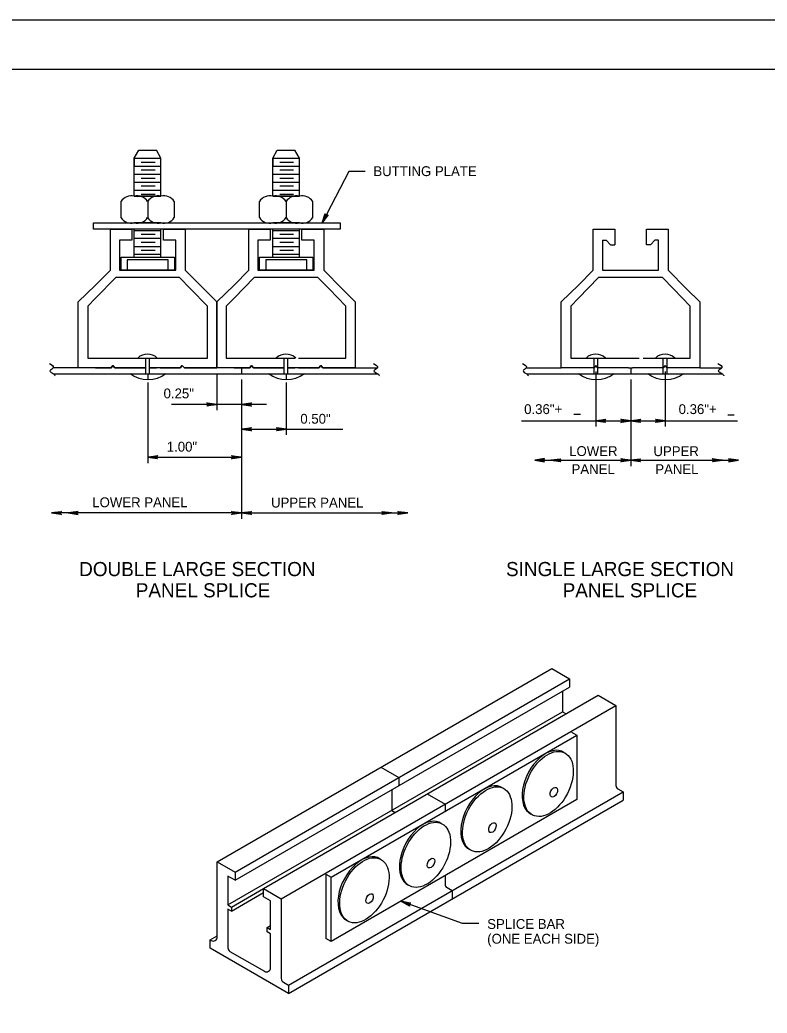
# Model space of a CAD drawing. Extents: x 650495 to 652241, y 298458 to 299646.
# Drawn here: x 651586.1 to 651813.4, y 299343.6 to 299645.6 of the extents above; entities that cross this region are included whole.
import ezdxf

# ---------------------------------------------------------------- set-up
doc = ezdxf.new("R2010")
doc.units = 0
for name, color, linetype in [('1', 7, 'Continuous'), ('2', 7, 'Continuous'), ('3', 7, 'Continuous'), ('PLT-BNDY', 7, 'Continuous')]:
    doc.layers.add(name, color=color, linetype=linetype)

# ---------------------------------------------------------------- blocks, each defined once
blk = doc.blocks.new('RARROW')
at = {"layer": '3'}
blk.add_lwpolyline([(-2.2695, 0.285), (-2.184875, 0.12075), (0, 0), (-2.2695, 0.285), (-2.38575, 0.384625), (0, 0), (-2.183125, -0.108), (-2.262875, -0.2705), (0, 0), (-2.38575, -0.379125), (-2.262875, -0.2705)], dxfattribs=at)

msp = doc.modelspace()

# ---------------------------------------------------------------- linework, layer by layer
at = {"layer": '1'}
msp.add_line((651376.31, 299630.63), (652162.31, 299630.63), dxfattribs=at)
at = {"layer": '2'}
for p, q in [((651620.9, 299603.62), (651622.28, 299606)), ((651622.28, 299606), (651627.65, 299606)), ((651629.03, 299603.62), (651627.65, 299606)), ((651663.03, 299603.62), (651664.4, 299606)), ((651664.4, 299606), (651669.78, 299606)), ((651671.15, 299603.62), (651669.78, 299606)), ((651620.9, 299603.62), (651629.03, 299603.62)), ((651620.9, 299603.62), (651620.9, 299601.12)), ((651620.9, 299592), (651620.9, 299603.62)), ((651629.03, 299592), (651629.03, 299603.62)), ((651663.03, 299603.62), (651671.15, 299603.62)), ((651663.03, 299603.62), (651663.03, 299601.12)), ((651663.03, 299592), (651663.03, 299603.62)), ((651671.15, 299592), (651671.15, 299603.62)), ((651620.9, 299601.12), (651629.03, 299601.12)), ((651623.03, 299602.37), (651627.28, 299602.37)), ((651623.03, 299600), (651627.28, 299600)), ((651663.03, 299601.12), (651671.15, 299601.12)), ((651665.15, 299602.37), (651669.4, 299602.37)), ((651665.15, 299600), (651669.4, 299600)), ((651620.9, 299598.75), (651629.03, 299598.75)), ((651623.03, 299597.5), (651627.28, 299597.5)), ((651663.03, 299598.75), (651671.15, 299598.75)), ((651665.15, 299597.5), (651669.4, 299597.5)), ((651620.9, 299596.25), (651629.03, 299596.25)), ((651620.9, 299593.87), (651629.03, 299593.87)), ((651623.03, 299595.12), (651627.28, 299595.12)), ((651663.03, 299596.25), (651671.15, 299596.25)), ((651663.03, 299593.87), (651671.15, 299593.87)), ((651665.15, 299595.12), (651669.4, 299595.12)), ((651616.9, 299585.5), (651616.9, 299590.37)), ((651620.9, 299592), (651629.03, 299592)), ((651629.03, 299592), (651620.9, 299592)), ((651623.03, 299592.62), (651627.28, 299592.62)), ((651625.03, 299590.37), (651625.03, 299585.5)), ((651633.15, 299585.5), (651633.15, 299590.37)), ((651659.03, 299585.5), (651659.03, 299590.37)), ((651663.03, 299592), (651671.15, 299592)), ((651671.15, 299592), (651663.03, 299592)), ((651665.15, 299592.62), (651669.4, 299592.62)), ((651667.15, 299590.37), (651667.15, 299585.5)), ((651675.28, 299585.5), (651675.28, 299590.37)), ((651629.03, 299583.87), (651620.9, 299583.87)), ((651620.9, 299573.5), (651620.9, 299582)), ((651620.9, 299581.62), (651629.03, 299581.62)), ((651629.03, 299573.5), (651629.03, 299582)), ((651671.15, 299583.87), (651663.03, 299583.87)), ((651663.03, 299573.5), (651663.03, 299582)), ((651663.03, 299581.62), (651671.15, 299581.62)), ((651671.15, 299573.5), (651671.15, 299582)), ((651760.53, 299571.12), (651760.53, 299582)), ((651760.53, 299582), (651767.03, 299582)), ((651767.03, 299582), (651767.03, 299577.25)), ((651776.66, 299577.25), (651776.66, 299582)), ((651776.66, 299582), (651783.28, 299582)), ((651783.28, 299582), (651783.28, 299572.25)), ((651620.9, 299579.25), (651629.03, 299579.25)), ((651623.03, 299580.5), (651627.28, 299580.5)), ((651663.03, 299579.25), (651671.15, 299579.25)), ((651665.15, 299580.5), (651669.4, 299580.5)), ((651763.28, 299578.62), (651764.41, 299578.62)), ((651763.28, 299578.62), (651763.28, 299569.5)), ((651765.78, 299577.25), (651764.41, 299578.62)), ((651777.91, 299577.25), (651779.28, 299578.62)), ((651780.41, 299578.62), (651779.28, 299578.62)), ((651780.41, 299569.5), (651780.41, 299578.62)), ((651620.9, 299576.75), (651629.03, 299576.75)), ((651623.03, 299578), (651627.28, 299578)), ((651623.03, 299575.62), (651627.28, 299575.62)), ((651663.03, 299576.75), (651671.15, 299576.75)), ((651665.15, 299578), (651669.4, 299578)), ((651665.15, 299575.62), (651669.4, 299575.62)), ((651765.78, 299577.25), (651767.03, 299577.25)), ((651777.91, 299577.25), (651776.66, 299577.25)), ((651616.9, 299569.5), (651616.9, 299573.5)), ((651616.9, 299573.5), (651633.15, 299573.5)), ((651620.9, 299574.37), (651629.03, 299574.37)), ((651633.15, 299573.5), (651633.15, 299569.5)), ((651659.03, 299569.5), (651659.03, 299573.5)), ((651659.03, 299573.5), (651675.28, 299573.5)), ((651663.03, 299574.37), (651671.15, 299574.37)), ((651675.28, 299573.5), (651675.28, 299569.5)), ((651633.15, 299569.5), (651616.9, 299569.5)), ((651675.28, 299569.5), (651659.03, 299569.5)), ((651763.28, 299569.5), (651780.41, 299569.5)), ((651624.4, 299538), (651624.4, 299542.75)), ((651625.53, 299538), (651625.53, 299542.75)), ((651666.53, 299538), (651666.53, 299542.75)), ((651667.65, 299538), (651667.65, 299542.75)), ((651760.78, 299538), (651760.78, 299542.75)), ((651761.91, 299538), (651761.91, 299542.75)), ((651781.78, 299538), (651781.78, 299542.75)), ((651783.03, 299538), (651783.03, 299542.75)), ((651603.9, 299539.87), (651596.28, 299539.87)), ((651653.53, 299539.87), (651653.53, 299538)), ((651688.15, 299539.87), (651694.9, 299539.87)), ((651740.16, 299539.87), (651750.78, 299539.87)), ((651771.28, 299539.87), (651772.41, 299539.87)), ((651771.91, 299539.87), (651771.91, 299538)), ((651792.91, 299539.87), (651799.66, 299539.87)), ((651596.28, 299538), (651695.03, 299538)), ((651625.03, 299538), (651625.03, 299536.26)), ((651646.03, 299538.12), (651646.03, 299526.93)), ((651653.53, 299536.25), (651653.53, 299493.86)), ((651666.53, 299538), (651667.65, 299538)), ((651667.15, 299538), (651667.15, 299536.26)), ((651740.28, 299538), (651799.78, 299538)), ((651760.78, 299538), (651761.91, 299538)), ((651761.28, 299538.75), (651761.28, 299521.95)), ((651771.28, 299538), (651772.41, 299538)), ((651771.91, 299536.25), (651771.91, 299509.95)), ((651781.78, 299538), (651783.03, 299538)), ((651782.41, 299538.75), (651782.41, 299521.95)), ((651625.03, 299535.41), (651625.03, 299510.88)), ((651667.15, 299535.36), (651667.15, 299519.41)), ((651646.03, 299528.68), (651632.28, 299528.68)), ((651661.12, 299528.68), (651646.03, 299528.68)), ((651756.6, 299525.58), (651754.6, 299525.58)), ((651803.39, 299525.39), (651801.4, 299525.39)), ((651653.53, 299521.16), (651684.31, 299521.16)), ((651738.72, 299523.7), (651804.39, 299523.7)), ((651782.41, 299523.7), (651782.41, 299523.7)), ((651625.03, 299512.63), (651653.53, 299512.63)), ((651743.17, 299511.7), (651771.91, 299511.7)), ((651771.91, 299511.7), (651803.33, 299511.7)), ((651653.53, 299495.68), (651595.78, 299495.68)), ((651653.53, 299495.68), (651704.13, 299495.68)), ((651646.16, 299389.62), (651747.92, 299448.37)), ((651651.57, 299386.49), (651753.33, 299445.24)), ((651651.57, 299383.99), (651753.33, 299442.74)), ((651660.24, 299381.49), (651761.99, 299440.24)), ((651665.65, 299378.37), (651767.41, 299437.12)), ((651649.41, 299376.49), (651751.17, 299435.24)), ((651753.87, 299429.02), (651755.5, 299428.08)), ((651751.72, 299422.82), (651751.72, 299422.82)), ((651667.81, 299352.12), (651769.57, 299410.87)), ((651733.05, 299412.04), (651733.05, 299412.04)), ((651667.81, 299349.62), (651769.57, 299408.37)), ((651755.5, 299408.52), (651755.5, 299408.52)), ((651741.62, 299404.1), (651741.62, 299404.1)), ((651714.38, 299401.26), (651714.38, 299401.26)), ((651736.82, 299397.74), (651736.82, 299397.74)), ((651722.95, 299393.32), (651722.95, 299393.32)), ((651646.16, 299389.62), (651646.16, 299389.62)), ((651695.7, 299390.48), (651695.7, 299390.48)), ((651679.18, 299385.89), (651679.18, 299366.33)), ((651679.18, 299385.89), (651680.8, 299384.95)), ((651718.15, 299386.96), (651718.15, 299386.96)), ((651704.28, 299382.54), (651704.28, 299382.54)), ((651650.49, 299375.87), (651660.24, 299381.49)), ((651650.49, 299374.62), (651660.24, 299380.24)), ((651699.48, 299376.17), (651699.48, 299376.17)), ((651661.32, 299369.62), (651662.4, 299370.24)), ((651685.6, 299371.76), (651685.6, 299371.76)), ((651644, 299365.87), (651646.16, 299367.12)), ((651680.8, 299365.39), (651679.18, 299366.33)), ((651680.8, 299365.39), (651680.8, 299365.39)), ((651650.03, 299362.38), (651660.53, 299356.33))]:
    msp.add_line(p, q, dxfattribs=at)
for points in [[(651691.15, 299599.5), (651686.15, 299599.5), (651678.09, 299583.87)], [(651613.65, 299571.12), (651613.65, 299582), (651620.15, 299582), (651620.15, 299578.62), (651616.4, 299578.62), (651616.4, 299571.12)], [(651633.53, 299572.25), (651633.53, 299578.62), (651629.78, 299578.62), (651629.78, 299582), (651636.4, 299582), (651636.4, 299572.25)], [(651655.78, 299571.12), (651655.78, 299582), (651662.28, 299582), (651662.28, 299578.62), (651658.53, 299578.62), (651658.53, 299571.12)], [(651675.65, 299572.25), (651675.65, 299578.62), (651671.9, 299578.62), (651671.9, 299582), (651678.53, 299582), (651678.53, 299572.25)], [(651628.78, 299569.5), (651633.53, 299569.5), (651633.53, 299572.25)], [(651636.4, 299572.25), (651636.4, 299569.5), (651642.03, 299563.87)], [(651670.9, 299569.5), (651675.65, 299569.5), (651675.65, 299572.25)], [(651678.53, 299572.25), (651678.53, 299569.5), (651684.15, 299563.87)], [(651783.28, 299572.25), (651783.28, 299569.5), (651788.91, 299563.87)], [(651609.15, 299565), (651613.65, 299569.5), (651613.65, 299571.12)], [(651616.4, 299571.12), (651616.4, 299569.5), (651623.78, 299569.5)], [(651623.78, 299569.5), (651625.03, 299569.5)], [(651625.03, 299569.5), (651628.78, 299569.5)], [(651651.28, 299565), (651655.78, 299569.5), (651655.78, 299571.12)], [(651658.53, 299571.12), (651658.53, 299569.5), (651665.9, 299569.5)], [(651665.9, 299569.5), (651667.15, 299569.5)], [(651667.15, 299569.5), (651670.9, 299569.5)], [(651756.03, 299565), (651760.53, 299569.5), (651760.53, 299571.12)], [(651771.91, 299569.5), (651775.66, 299569.5)], [(651615.28, 299567.25), (651609.15, 299561)], [(651623.78, 299567.25), (651615.28, 299567.25)], [(651625.03, 299567.25), (651623.78, 299567.25)], [(651628.78, 299567.25), (651625.03, 299567.25)], [(651634.65, 299567.25), (651628.78, 299567.25)], [(651638.03, 299563.87), (651634.65, 299567.25)], [(651657.4, 299567.25), (651651.28, 299561)], [(651665.9, 299567.25), (651657.4, 299567.25)], [(651667.15, 299567.25), (651665.9, 299567.25)], [(651670.9, 299567.25), (651667.15, 299567.25)], [(651676.78, 299567.25), (651670.9, 299567.25)], [(651680.15, 299563.87), (651676.78, 299567.25)], [(651762.16, 299567.25), (651756.03, 299561)], [(651770.66, 299567.25), (651762.16, 299567.25)], [(651771.91, 299567.25), (651770.66, 299567.25)], [(651775.66, 299567.25), (651771.91, 299567.25)], [(651781.53, 299567.25), (651775.66, 299567.25)], [(651784.91, 299563.87), (651781.53, 299567.25)], [(651609.15, 299539.87), (651603.9, 299539.87), (651603.9, 299559.87), (651609.15, 299565)], [(651643.15, 299549.62), (651643.15, 299558.62), (651638.03, 299563.87)], [(651642.03, 299563.87), (651646.03, 299559.87), (651646.03, 299549.62)], [(651651.28, 299539.87), (651646.03, 299539.87), (651646.03, 299559.87), (651651.28, 299565)], [(651685.28, 299549.62), (651685.28, 299558.62), (651680.15, 299563.87)], [(651684.15, 299563.87), (651688.15, 299559.87), (651688.15, 299549.62)], [(651756.03, 299539.87), (651750.78, 299539.87), (651750.78, 299559.87), (651756.03, 299565)], [(651790.03, 299549.62), (651790.03, 299558.62), (651784.91, 299563.87)], [(651788.91, 299563.87), (651792.91, 299559.87), (651792.91, 299549.62)], [(651609.15, 299561), (651606.78, 299558.62), (651606.78, 299542.75), (651609.15, 299542.75)], [(651651.28, 299561), (651648.9, 299558.62), (651648.9, 299542.75), (651651.28, 299542.75)], [(651756.03, 299561), (651753.66, 299558.62), (651753.66, 299542.75), (651756.03, 299542.75)], [(651628.78, 299542.75), (651643.15, 299542.75), (651643.15, 299549.62)], [(651646.03, 299549.62), (651646.03, 299539.87), (651636.15, 299539.87), (651635.53, 299540.5), (651634.9, 299539.87), (651628.78, 299539.87)], [(651670.9, 299542.75), (651685.28, 299542.75), (651685.28, 299549.62)], [(651688.15, 299549.62), (651688.15, 299539.87), (651678.28, 299539.87), (651677.65, 299540.5), (651677.03, 299539.87), (651670.9, 299539.87)], [(651775.66, 299542.75), (651790.03, 299542.75), (651790.03, 299549.62)], [(651792.91, 299549.62), (651792.91, 299539.87), (651783.03, 299539.87), (651782.41, 299540.5), (651781.78, 299539.87), (651775.66, 299539.87)], [(651609.15, 299542.75), (651625.03, 299542.75)], [(651625.03, 299542.75), (651627.65, 299542.75)], [(651627.65, 299542.75), (651628.78, 299542.75)], [(651651.28, 299542.75), (651667.15, 299542.75)], [(651667.15, 299542.75), (651669.78, 299542.75)], [(651756.03, 299542.75), (651771.91, 299542.75)], [(651771.91, 299542.75), (651774.53, 299542.75)], [(651609.15, 299539.87), (651603.9, 299539.87)], [(651609.15, 299539.87), (651613.9, 299539.87), (651614.4, 299540.5), (651615.03, 299539.87), (651624.4, 299539.87)], [(651624.4, 299539.87), (651615.03, 299539.87), (651614.4, 299540.5), (651613.9, 299539.87), (651609.15, 299539.87)], [(651625.53, 299539.87), (651627.65, 299539.87)], [(651627.65, 299539.87), (651625.53, 299539.87)], [(651628.78, 299539.87), (651627.65, 299539.87)], [(651628.78, 299539.87), (651627.65, 299539.87)], [(651628.78, 299539.87), (651634.9, 299539.87), (651635.53, 299540.5), (651636.15, 299539.87), (651646.03, 299539.87)], [(651651.28, 299539.87), (651646.03, 299539.87)], [(651651.28, 299539.87), (651656.03, 299539.87), (651656.53, 299540.5), (651657.15, 299539.87), (651666.53, 299539.87)], [(651666.53, 299539.87), (651657.15, 299539.87), (651656.53, 299540.5), (651656.03, 299539.87), (651651.28, 299539.87)], [(651667.65, 299539.87), (651669.78, 299539.87)], [(651667.65, 299539.87), (651669.78, 299539.87)], [(651669.78, 299539.87), (651667.65, 299539.87)], [(651670.9, 299539.87), (651669.78, 299539.87)], [(651670.9, 299539.87), (651669.78, 299539.87)], [(651670.9, 299539.87), (651669.78, 299539.87)], [(651670.9, 299539.87), (651677.03, 299539.87), (651677.65, 299540.5), (651678.28, 299539.87), (651688.15, 299539.87)], [(651756.03, 299539.87), (651750.78, 299539.87)], [(651771.28, 299539.87), (651761.91, 299539.87), (651761.28, 299540.5), (651760.78, 299539.87), (651756.03, 299539.87)], [(651774.53, 299539.87), (651772.41, 299539.87)], [(651775.66, 299539.87), (651774.53, 299539.87)], [(651747.92, 299448.37), (651753.33, 299445.24), (651753.33, 299442.74)], [(651751.17, 299441.49), (651751.17, 299435.24), (651752.25, 299434.62)], [(651761.99, 299440.24), (651767.41, 299437.12), (651767.41, 299412.84)], [(651680.8, 299384.95), (651755.5, 299428.08), (651755.5, 299408.52), (651680.8, 299365.39), (651680.8, 299384.95)], [(651695.96, 299418.37), (651701.37, 299415.24), (651701.37, 299412.74)], [(651699.21, 299411.49), (651699.21, 299405.24), (651700.29, 299404.62)], [(651710.03, 299410.24), (651715.44, 299407.12), (651715.44, 299404.95)], [(651768.03, 299411.76), (651769.57, 299410.87), (651769.57, 299408.37)], [(651646.16, 299366.78), (651646.16, 299389.62), (651651.57, 299386.49), (651651.57, 299383.99), (651649.41, 299385.24), (651649.41, 299376.49), (651650.49, 299375.87), (651650.49, 299374.62), (651649.41, 299375.24), (651649.41, 299363.47)], [(651715.44, 299385.39), (651715.44, 299382.84)], [(651662.4, 299357.41), (651662.4, 299367.74), (651661.32, 299368.37), (651661.32, 299369.62), (651662.4, 299368.99), (651662.4, 299377.74), (651660.24, 299378.99), (651660.24, 299381.49), (651665.65, 299378.37), (651665.65, 299354.09)], [(651716.07, 299381.76), (651717.61, 299380.87), (651717.61, 299378.37)], [(651725.71, 299370.81), (651720.71, 299370.81), (651702.03, 299377.65)], [(651666.27, 299353.01), (651667.81, 299352.12), (651667.81, 299349.62), (651644, 299363.37), (651644, 299365.87), (651644.29, 299365.7)]]:
    msp.add_lwpolyline(points, dxfattribs=at)
for points in [[(651608.53, 299582), (651608.53, 299583.87), (651683.53, 299583.87), (651683.53, 299582)], [(651631.28, 299569.5), (651631.28, 299572.62), (651618.78, 299572.62), (651618.78, 299569.5)], [(651673.4, 299569.5), (651673.4, 299572.62), (651660.9, 299572.62), (651660.9, 299569.5)]]:
    msp.add_lwpolyline(points, close=True, dxfattribs=at)
for centre, radius, start, end in [((651620.04, 299588.31), 3.8, 76.6866, 146.9162), ((651621.79, 299588.31), 3.8, 33.0838, 103.3134), ((651628.17, 299588.31), 3.8, 76.6866, 146.9162), ((651629.92, 299588.31), 3.8, 33.0838, 103.3134), ((651662.16, 299588.31), 3.8, 76.6866, 146.9162), ((651663.92, 299588.31), 3.8, 33.0838, 103.3134), ((651670.29, 299588.31), 3.8, 76.6866, 146.9162), ((651672.04, 299588.31), 3.8, 33.0838, 103.3134), ((651620.04, 299587.58), 3.8, 213.0838, 283.3134), ((651621.79, 299587.58), 3.8, 256.6866, 326.9162), ((651628.17, 299587.58), 3.8, 213.0838, 283.3134), ((651629.92, 299587.58), 3.8, 256.6866, 326.9162), ((651662.16, 299587.58), 3.8, 213.0838, 283.3134), ((651663.92, 299587.58), 3.8, 256.6866, 326.9162), ((651670.29, 299587.58), 3.8, 213.0838, 283.3134), ((651672.04, 299587.58), 3.8, 256.6866, 326.9162), ((651624.95, 299539.77), 4.23, 45.7805, 134.2195), ((651667.07, 299539.77), 4.23, 45.7805, 134.2195), ((651761.28, 299539.77), 4.23, 45.7805, 134.2195), ((651782.37, 299539.77), 4.23, 45.7805, 134.2195), ((651625.11, 299545.27), 9.01, 232.6949, 307.3051), ((651667.23, 299545.27), 9.01, 232.6949, 307.3051), ((651761.44, 299545.27), 9.01, 232.6949, 307.3051), ((651782.53, 299545.27), 9.01, 232.6949, 307.3051), ((651768.66, 299412.84), 1.25, 180, 239.9993), ((651716.69, 299382.84), 1.25, 180, 239.9993), ((651644.91, 299366.78), 1.25, 239.9993, 0), ((651650.66, 299363.47), 1.25, 180, 240.0002), ((651661.15, 299357.41), 1.25, 239.9999, 0), ((651666.9, 299354.09), 1.25, 180, 239.9993)]:
    msp.add_arc(centre, radius, start, end, dxfattribs=at)
for centre, major_axis in [((651746.94, 299413.3), (4.9, 9.45)), ((651728.27, 299402.52), (4.9, 9.45)), ((651748.52, 299410.78), (0.74, 1.42)), ((651709.6, 299391.74), (4.9, 9.45)), ((651729.85, 299400), (0.74, 1.42)), ((651690.92, 299380.96), (4.9, 9.45)), ((651711.17, 299389.22), (0.74, 1.42)), ((651692.5, 299378.44), (0.74, 1.42))]:
    msp.add_ellipse(centre, major_axis=major_axis, ratio=0.602781, dxfattribs=at)
for centre in [(651746.4, 299413.62), (651727.73, 299402.83), (651709.06, 299392.05), (651690.38, 299381.27)]:
    msp.add_ellipse(centre, major_axis=(4.9, 9.45), ratio=0.602781, start_param=6.207238, end_param=9.446163, dxfattribs=at)
for points in [[(651595.15, 299541.12), (651596.28, 299539.87), (651595.28, 299538.87), (651596.4, 299538), (651596.9, 299537.37)], [(651693.65, 299541.12), (651694.9, 299539.87), (651693.78, 299538.87), (651695.03, 299538), (651695.53, 299537.37)], [(651739.03, 299541.12), (651740.16, 299539.87), (651739.16, 299538.87), (651740.28, 299538), (651740.78, 299537.37)], [(651798.41, 299541.12), (651799.66, 299539.87), (651798.53, 299538.87), (651799.78, 299538), (651800.28, 299537.37)]]:
    msp.add_spline(points, degree=3, dxfattribs=at)
at = {"layer": 'PLT-BNDY'}
msp.add_lwpolyline([(651336.31, 299645.63), (652177.31, 299645.63), (652177.31, 299051.63), (651336.31, 299051.63)], close=True, dxfattribs=at)

# ---------------------------------------------------------------- block references
at = {"layer": '2', "xscale": 1.2574347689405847}
for p, yscale, rotation in [((651678.09, 299583.87), 1.3092961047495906, -117.30666422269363), ((651653.53, 299528.68), 1.3092961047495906, 180), ((651761.28, 299523.7), 1.3092961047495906, 180), ((651771.91, 299523.7), 1.3092961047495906, 180), ((651653.53, 299521.16), 1.3092961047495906, 180), ((651625.03, 299512.63), 1.3092961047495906, 180), ((651742.71, 299511.7), -1.3092961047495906, -180), ((651747.66, 299511.7), 1.3092961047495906, 180), ((651771.91, 299511.7), 1.3092961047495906, 180), ((651595.78, 299495.68), 1.3092961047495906, 180), ((651600.83, 299495.68), -1.3092961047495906, -180), ((651653.53, 299495.68), 1.3092961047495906, 180), ((651702.03, 299377.65), 1.3092961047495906, 159.89547322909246)]:
    msp.add_blockref('RARROW', p, dxfattribs=dict(at, yscale=yscale, rotation=rotation))
for p, yscale in [((651646.03, 299528.68), 1.3092961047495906), ((651771.91, 299523.7), 1.3092961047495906), ((651782.41, 299523.7), 1.3092961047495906), ((651667.15, 299521.16), 1.3092961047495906), ((651653.53, 299512.63), 1.3092961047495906), ((651771.91, 299511.7), 1.3092961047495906), ((651799.78, 299511.7), 1.3092961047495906), ((651804.68, 299511.7), -1.3092961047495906), ((651653.53, 299495.68), 1.3092961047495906), ((651699.2, 299495.68), 1.3092961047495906), ((651704.13, 299495.68), 1.3092961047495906)]:
    msp.add_blockref('RARROW', p, dxfattribs=dict(at, yscale=yscale))

# ---------------------------------------------------------------- texts
at = {"layer": '2'}
for s, height, p in [('BUTTING PLATE', 2.9992, (651693.65, 299598.12)), ('0.25"', 3, (651629.84, 299530.54)), ('0.36"+', 3, (651739.5, 299525.76)), ('0.36"+', 3, (651786.48, 299525.76)), ('0.50"', 3, (651671.43, 299522.83)), (' 1.00"', 3, (651629.69, 299514.34)), ('LOWER', 2.999, (651753.2, 299513)), ('UPPER', 2.999, (651778.82, 299512.98)), ('PANEL', 2.999, (651753.91, 299507.51)), ('PANEL', 2.999, (651779.38, 299507.49)), ('LOWER PANEL', 2.9992, (651608.15, 299497.43)), ('UPPER PANEL', 2.9992, (651662.53, 299497.34)), ('DOUBLE LARGE SECTION', 4.3, (651604.17, 299476.48)), ('SINGLE LARGE SECTION', 4.3, (651733.99, 299476.48)), ('PANEL SPLICE', 4.3, (651621.39, 299470.03)), ('PANEL SPLICE', 4.3, (651751.21, 299470.03))]:
    msp.add_text(s, height=height, dxfattribs=at).set_placement(p)
at = {"layer": '3'}
for s, p in [('SPLICE BAR', (651728.26, 299369.22)), ('(ONE EACH SIDE)', (651728.26, 299364.72))]:
    msp.add_text(s, height=3, dxfattribs=at).set_placement(p)

doc.saveas('drawing.dxf')
